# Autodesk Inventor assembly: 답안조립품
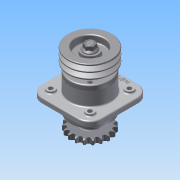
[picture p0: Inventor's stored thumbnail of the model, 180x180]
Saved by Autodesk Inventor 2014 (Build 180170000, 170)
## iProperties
Created: 2015-09
Part Number: 답안조립품
Document SubType Name: Assembly
Designer: study
Author: study
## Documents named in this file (12)
- C:\Users\study\Desktop\450909V1011\답안조립품.iam
- C:\Users\study\Desktop\450909V1011\1-본체.ipt
- C:\Users\study\Desktop\450909V1011\2-커버.ipt
- C:\Users\study\Desktop\450909V1011\3-축.ipt
- C:\Users\study\Desktop\450909V1011\6-베어링 6206.ipt
- C:\Users\study\Desktop\450909V1011\11-키 6x6.ipt
- C:\Users\study\Desktop\450909V1011\8-오일실 30x42.ipt
- C:\Users\study\Desktop\450909V1011\7-부시.ipt
- C:\Users\study\Desktop\450909V1011\10-M6.ipt
- C:\Users\study\Desktop\450909V1011\4-V벨트풀리.ipt
- C:\Users\study\Desktop\450909V1011\9-M16-너트.ipt
- C:\Users\study\Desktop\450909V1011\5-체인 스프로킷.ipt
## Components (23 placed, 11 different names)
1. 1-본체:1
2. 2-커버:1
3. 2-커버:2
4. 3-축:1 — 각도:1, 각도:2
5. 6-베어링 6206:1
6. 6-베어링 6206:2
7. 11-키 6x6:1 — 각도:1, 각도:3
8. 11-키 6x6:2 — 각도:2, 각도:4
9. 8-8-오일실 30x42:1
10. 8-8-오일실 30x42:2
11. 7-부시:1
12. 4-V벨트풀리:1 — 각도:3
13. 9-M16 너트:1
14. 5-체인 스프로킷:1 — 각도:4
15. 9-M16 너트:2
16. 10-M6:1
17. 10-M6:2
18. 10-M6:3
19. 10-M6:4
20. 10-M6:5
21. 10-M6:6
22. 10-M6:7
23. 10-M6:8
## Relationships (4: Angle 4)
- 각도:1 [Angle]: 3-축:1 ↔ 11-키 6x6:1
- 각도:2 [Angle]: 3-축:1 ↔ 11-키 6x6:2
- 각도:3 [Angle]: 11-키 6x6:1 ↔ 4-V벨트풀리:1
- 각도:4 [Angle]: 11-키 6x6:2 ↔ 5-체인 스프로킷:1
